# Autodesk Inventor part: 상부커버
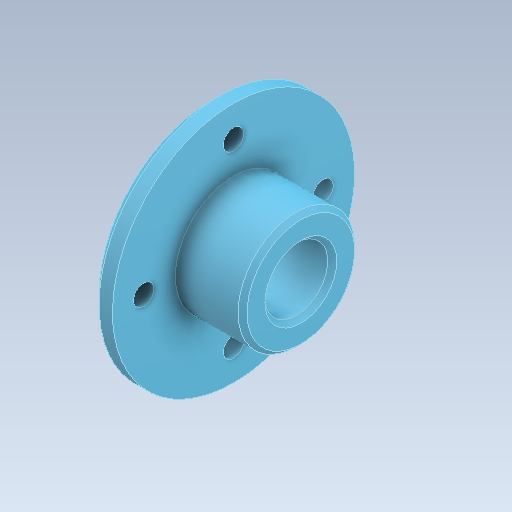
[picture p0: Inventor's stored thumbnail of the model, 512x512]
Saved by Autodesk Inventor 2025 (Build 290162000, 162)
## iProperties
Created: 2024-07
Part Number: 상부커버
Material: 알루미늄 6061
Document SubType Name: Modeling
Designer: 미서니
Density: 2.71 g/cm^3
Appearance: 기본값
Author: jhkim
Sending System: Autodesk Inventor 2025
Preprocessor: ST-DEVELOPER v20
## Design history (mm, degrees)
feature "솔리드1"
node "솔리드2"
